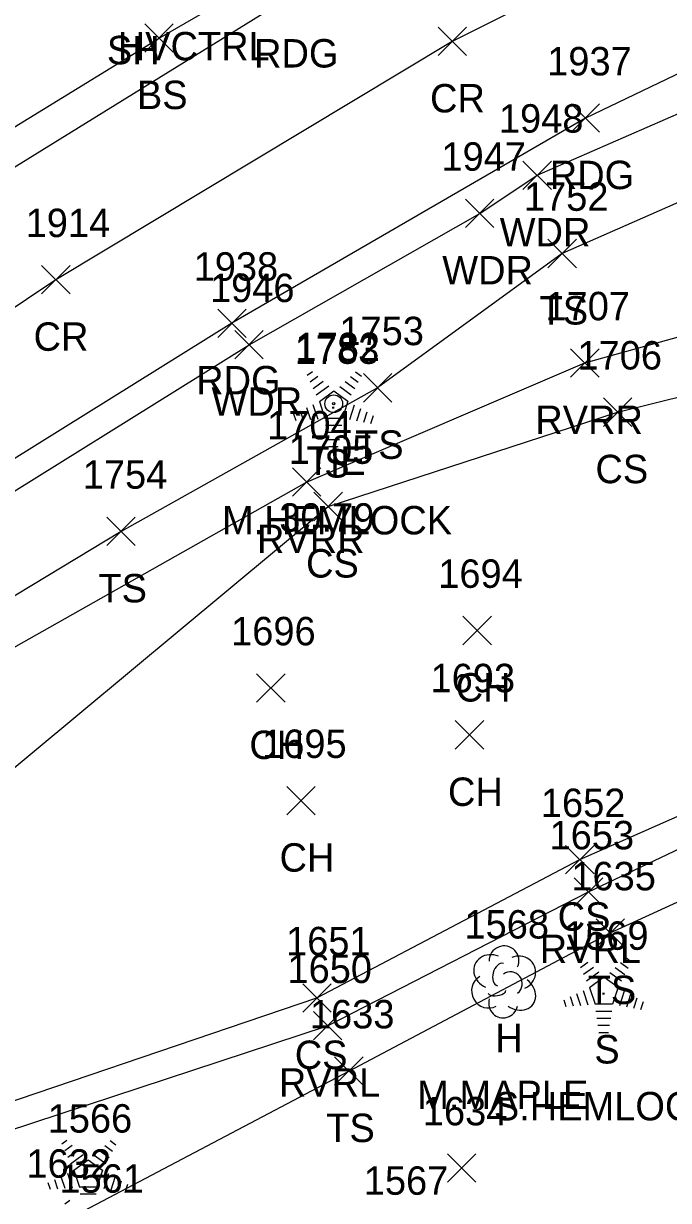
# Model space of a CAD drawing. Extents: x 1621633 to 1624015, y 417863 to 420979.
# Drawn here: x 1621720.8 to 1621766.2, y 417953.8 to 418036.6 of the extents above; entities that cross this region are included whole.
import ezdxf

# ---------------------------------------------------------------- set-up
doc = ezdxf.new("R2010")
doc.units = 0
for name, color, linetype in [('C_A', 7, 'Continuous'), ('C_C', 7, 'Continuous'), ('C_I', 7, 'Continuous'), ('CBP', 7, 'Continuous'), ('L_A', 7, 'Continuous'), ('L_C', 7, 'Continuous'), ('L_I', 7, 'Continuous'), ('L_TIC', 7, 'Continuous'), ('LAWA', 7, 'Continuous'), ('LAWE', 7, 'Continuous'), ('LELB', 7, 'Continuous'), ('LTC', 7, 'Continuous'), ('LTD', 7, 'Continuous'), ('P_A', 7, 'Continuous'), ('P_I', 7, 'Continuous'), ('P_TIC', 7, 'Continuous'), ('PEU', 7, 'Continuous'), ('PRC', 7, 'Continuous')]:
    doc.layers.add(name, color=color, linetype=linetype)

msp = doc.modelspace()

# ---------------------------------------------------------------- linework, layer by layer
at = {"layer": 'CBP'}
for radius in [0.625, 0.0833]:
    msp.add_circle((1621742.603, 418009.803), radius, dxfattribs=at)
at = {"layer": 'L_TIC'}
for points in [[(1621729.307, 418034.534), (1621731.307, 418036.534)], [(1621731.307, 418034.534), (1621729.307, 418036.534)], [(1621755.92, 418024.879), (1621757.92, 418026.879)], [(1621757.92, 418024.879), (1621755.92, 418026.879)], [(1621751.876, 418022.199), (1621753.876, 418024.199)], [(1621753.876, 418022.199), (1621751.876, 418024.199)], [(1621757.68, 418019.378), (1621759.68, 418021.378)], [(1621759.68, 418019.378), (1621757.68, 418021.378)], [(1621735.638, 418012.959), (1621737.638, 418014.959)], [(1621737.638, 418012.959), (1621735.638, 418014.959)], [(1621759.276, 418011.676), (1621761.276, 418013.676)], [(1621761.276, 418011.676), (1621759.276, 418013.676)], [(1621744.692, 418009.927), (1621746.692, 418011.927)], [(1621746.692, 418009.927), (1621744.692, 418011.927)], [(1621761.579, 418008.214), (1621763.579, 418010.214)], [(1621763.579, 418008.214), (1621761.579, 418010.214)], [(1621739.687, 418003.296), (1621741.687, 418005.296)], [(1621741.687, 418003.296), (1621739.687, 418005.296)], [(1621741.211, 418001.577), (1621743.211, 418003.577)], [(1621743.211, 418001.577), (1621741.211, 418003.577)], [(1621726.629, 417999.827), (1621728.629, 418001.827)], [(1621728.629, 417999.827), (1621726.629, 418001.827)], [(1621751.698, 417992.853), (1621753.698, 417994.853)], [(1621753.698, 417992.853), (1621751.698, 417994.853)], [(1621737.173, 417988.809), (1621739.173, 417990.809)], [(1621739.173, 417988.809), (1621737.173, 417990.809)], [(1621751.155, 417985.509), (1621753.155, 417987.509)], [(1621753.155, 417985.509), (1621751.155, 417987.509)], [(1621739.299, 417980.884), (1621741.299, 417982.884)], [(1621741.299, 417980.884), (1621739.299, 417982.884)], [(1621758.92, 417976.729), (1621760.92, 417978.729)], [(1621760.92, 417976.729), (1621758.92, 417978.729)], [(1621759.532, 417974.456), (1621761.532, 417976.456)], [(1621761.532, 417974.456), (1621759.532, 417976.456)], [(1621761.067, 417971.573), (1621763.067, 417973.573)], [(1621763.067, 417971.573), (1621761.067, 417973.573)], [(1621740.418, 417967.002), (1621742.418, 417969.002)], [(1621742.418, 417967.002), (1621740.418, 417969.002)], [(1621741.172, 417965.049), (1621743.172, 417967.049)], [(1621743.172, 417965.049), (1621741.172, 417967.049)], [(1621742.664, 417961.858), (1621744.664, 417963.858)], [(1621744.664, 417961.858), (1621742.664, 417963.858)], [(1621750.612, 417955.037), (1621752.612, 417957.037)], [(1621752.612, 417955.037), (1621750.612, 417957.037)]]:
    msp.add_lwpolyline(points, dxfattribs=at)
at = {"layer": 'LAWA'}
msp.add_lwpolyline([(1621679.191, 417971.595), (1621702.483, 417990.446), (1621715.012, 418000.477), (1621736.638, 418013.959), (1621752.876, 418023.199), (1621756.92, 418025.879), (1621771.105, 418032.081), (1621799.594, 418044.877), (1621821.796, 418051.595), (1621846.965, 418058.282), (1621864.113, 418063.689), (1621891.562, 418069.816), (1621913.254, 418074.106), (1621937.152, 418070.696)], dxfattribs=at)
at = {"layer": 'LAWE'}
for points in [[(1621694.469, 417944.857), (1621713.846, 417956.733), (1621742.172, 417966.049), (1621760.532, 417975.456), (1621777.237, 417983.398), (1621792.696, 417991.301), (1621817.095, 418001.163), (1621844.467, 418008.037), (1621871.363, 418013.308), (1621897.422, 418019.495), (1621922.912, 418028.804), (1621945.859, 418038.978), (1621969.359, 418051.535), (1621990.012, 418069.674), (1621996.064, 418084.217), (1621996.533, 418092.287)], [(1621682.822, 417967.998), (1621698.064, 417979.126), (1621716.448, 417990.621), (1621740.687, 418004.296), (1621760.276, 418012.676), (1621779.786, 418018.1), (1621807.782, 418023.044), (1621832.841, 418028.899), (1621852.452, 418034.783), (1621876.37, 418040.125), (1621904.646, 418043.594), (1621931.259, 418052.925), (1621950.617, 418064.927), (1621964.804, 418074.349), (1621971.864, 418081.724)]]:
    msp.add_lwpolyline(points, dxfattribs=at)
at = {"layer": 'LELB'}
for points in [[(1621664.034, 417989.432), (1621687.487, 418007.656), (1621711.941, 418024.269), (1621730.307, 418035.534), (1621752.55, 418048.381), (1621767.69, 418055.001), (1621798.303, 418066.249), (1621826.915, 418075.928), (1621858.253, 418085.298), (1621888.981, 418092.531), (1621914.256, 418098.407), (1621930.996, 418100.467)], [(1621694.018, 417945.604), (1621713.058, 417958.392), (1621741.418, 417968.002), (1621759.92, 417977.729), (1621776.332, 417984.988), (1621792.046, 417992.579), (1621816.284, 418002.68), (1621844.088, 418009.589), (1621869.849, 418015.692), (1621896.837, 418021.913), (1621921.805, 418030.632), (1621944.897, 418041.057), (1621968.773, 418053.066), (1621989.111, 418070.538), (1621994.262, 418084.512), (1621994.522, 418092.07)], [(1621714.218, 417979.319), (1621742.211, 418002.577), (1621762.579, 418009.214), (1621780.28, 418013.608), (1621808.258, 418019.376), (1621833.473, 418026.83), (1621853.516, 418030.646), (1621878.098, 418035.973), (1621904.446, 418042.094), (1621933.372, 418049.997), (1621951.553, 418063.416), (1621967.003, 418072.955), (1621972.682, 418081.713), (1621977.304, 418089.793)], [(1621870.082, 418049.389), (1621847.864, 418048.319), (1621821.87, 418043.443), (1621810.848, 418041.046), (1621801.708, 418037.161), (1621779.745, 418029.631), (1621758.68, 418020.378), (1621745.692, 418010.927), (1621727.629, 418000.827), (1621708.748, 417989.428), (1621682.341, 417970.694)], [(1621696.619, 417939.068), (1621723.715, 417952.351), (1621743.664, 417962.858), (1621762.067, 417972.573), (1621786.253, 417983.66), (1621806.904, 417990.669), (1621831.079, 418002.462), (1621857.774, 418009.445), (1621874.764, 418010.395)]]:
    msp.add_lwpolyline(points, dxfattribs=at)
at = {"layer": 'LTC'}
for p, q in [((1621740.742, 418011.82), (1621741.097, 418012.078)), ((1621744.14, 418012.061), (1621744.56, 418011.756)), ((1621740.952, 418011.355), (1621741.481, 418011.739)), ((1621741.161, 418010.889), (1621741.865, 418011.4)), ((1621743.398, 418011.364), (1621744.078, 418010.87)), ((1621743.769, 418011.713), (1621744.319, 418011.313)), ((1621741.371, 418010.423), (1621742.249, 418011.061)), ((1621741.595, 418009.968), (1621742.607, 418010.703)), ((1621742.607, 418010.703), (1621743.604, 418009.978)), ((1621743.027, 418011.016), (1621743.837, 418010.427)), ((1621740.685, 418009.533), (1621740.957, 418008.698)), ((1621741.141, 418009.749), (1621741.472, 418008.73)), ((1621741.595, 418009.968), (1621741.983, 418008.775)), ((1621743.604, 418009.978), (1621743.213, 418008.775)), ((1621744.042, 418009.707), (1621743.704, 418008.668)), ((1621739.775, 418009.1), (1621739.927, 418008.632)), ((1621740.23, 418009.316), (1621740.442, 418008.665)), ((1621743.213, 418008.775), (1621741.983, 418008.775)), ((1621744.486, 418009.457), (1621744.199, 418008.572)), ((1621744.931, 418009.207), (1621744.694, 418008.477)), ((1621745.375, 418008.956), (1621745.188, 418008.382)), ((1621743.175, 418008.275), (1621742.03, 418008.275)), ((1621743.091, 418007.775), (1621742.103, 418007.775)), ((1621743.007, 418007.275), (1621742.175, 418007.275)), ((1621742.923, 418006.775), (1621742.248, 418006.775)), ((1621759.753, 417970.597), (1621760.107, 417970.854)), ((1621763.151, 417970.837), (1621763.57, 417970.532)), ((1621759.962, 417970.131), (1621760.491, 417970.515)), ((1621760.172, 417969.665), (1621760.876, 417970.177)), ((1621760.381, 417969.2), (1621761.26, 417969.837)), ((1621762.038, 417969.792), (1621762.847, 417969.203)), ((1621762.409, 417970.14), (1621763.088, 417969.647)), ((1621762.78, 417970.489), (1621763.329, 417970.09)), ((1621760.606, 417968.745), (1621761.618, 417969.479)), ((1621761.618, 417969.479), (1621762.615, 417968.754)), ((1621759.696, 417968.309), (1621759.967, 417967.474)), ((1621760.151, 417968.525), (1621760.482, 417967.506)), ((1621760.606, 417968.745), (1621760.993, 417967.551)), ((1621762.615, 417968.754), (1621762.223, 417967.551)), ((1621763.052, 417968.483), (1621762.714, 417967.444)), ((1621763.497, 417968.233), (1621763.209, 417967.348)), ((1621758.785, 417967.876), (1621758.937, 417967.408)), ((1621759.241, 417968.092), (1621759.452, 417967.441)), ((1621762.223, 417967.551), (1621760.993, 417967.551)), ((1621763.941, 417967.983), (1621763.704, 417967.253)), ((1621764.386, 417967.732), (1621764.199, 417967.158)), ((1621762.185, 417967.051), (1621761.041, 417967.051)), ((1621762.101, 417966.551), (1621761.113, 417966.551)), ((1621762.018, 417966.051), (1621761.186, 417966.051)), ((1621761.934, 417965.551), (1621761.259, 417965.551)), ((1621723.455, 417957.734), (1621723.81, 417957.992)), ((1621723.665, 417957.269), (1621724.194, 417957.653)), ((1621726.482, 417957.626), (1621727.032, 417957.227)), ((1621726.854, 417957.975), (1621727.273, 417957.67)), ((1621723.874, 417956.803), (1621724.578, 417957.314)), ((1621724.084, 417956.337), (1621724.962, 417956.975)), ((1621724.309, 417955.882), (1621725.32, 417956.617)), ((1621725.32, 417956.617), (1621726.317, 417955.892)), ((1621725.74, 417956.93), (1621726.55, 417956.341)), ((1621726.111, 417957.278), (1621726.791, 417956.784)), ((1621724.309, 417955.882), (1621724.696, 417954.689)), ((1621726.317, 417955.892), (1621725.926, 417954.689)), ((1621722.488, 417955.013), (1621722.64, 417954.545)), ((1621722.943, 417955.23), (1621723.155, 417954.578)), ((1621723.399, 417955.447), (1621723.67, 417954.611)), ((1621723.854, 417955.663), (1621724.185, 417954.644)), ((1621726.755, 417955.621), (1621726.417, 417954.581)), ((1621727.199, 417955.37), (1621726.912, 417954.486)), ((1621727.644, 417955.12), (1621727.407, 417954.391)), ((1621728.088, 417954.87), (1621727.901, 417954.296)), ((1621725.926, 417954.689), (1621724.696, 417954.689)), ((1621725.888, 417954.189), (1621724.743, 417954.189)), ((1621723.663, 417953.505), (1621724.018, 417953.763))]:
    msp.add_line(p, q, dxfattribs=at)
at = {"layer": 'LTD'}
msp.add_line((1621754.542, 417969.18), (1621754.542, 417969.18), dxfattribs=at)
msp.add_line((1621754.542, 417969.18), (1621754.542, 417969.18), dxfattribs=at)
msp.add_arc((1621754.589, 417970.614), 1.047, 335.52715, 180.95627, dxfattribs=at)
for centre, major_axis, ratio, start_param, end_param in [((1621753.75, 417969.846), (1.21, -0.512), 0.895232, 1.570796, 4.712389), ((1621755.584, 417969.763), (-1.141, -0.483), 0.949671, 1.570796, 4.712389), ((1621754.334, 417969.638), (-0.208, -0.792), 0.645439, 3.141593, 6.283185), ((1621755.042, 417969.013), (-0.5, 0.667), 0.989748, 3.141593, 6.283185), ((1621753.459, 417968.471), (0.584, -1.042), 0.959034, 3.141593, 6.283185), ((1621755.542, 417968.347), (-1.09, 0.792), 0.841452, 1.570796, 4.712389), ((1621754.084, 417968.43), (-0.625, -0.083), 0.423636, 0, 3.141593), ((1621754.542, 417967.68), (0.265, 1.061), 0.942809, 1.570796, 4.712389)]:
    msp.add_ellipse(centre, major_axis=major_axis, ratio=ratio, start_param=start_param, end_param=end_param, dxfattribs=at)
at = {"layer": 'P_TIC'}
for points in [[(1621749.947, 418034.3), (1621751.947, 418036.3)], [(1621751.947, 418034.3), (1621749.947, 418036.3)], [(1621759.318, 418028.904), (1621761.318, 418030.904)], [(1621761.318, 418028.904), (1621759.318, 418030.904)], [(1621722.041, 418017.53), (1621724.041, 418019.53)], [(1621724.041, 418017.53), (1621722.041, 418019.53)], [(1621734.432, 418014.464), (1621736.432, 418016.464)], [(1621736.432, 418014.464), (1621734.432, 418016.464)]]:
    msp.add_lwpolyline(points, dxfattribs=at)
at = {"layer": 'PEU'}
for points in [[(1621666.087, 417987.333), (1621690.601, 418006.329), (1621714.112, 418022.734), (1621739.503, 418038.461), (1621766, 418052.456), (1621797.985, 418064.445), (1621829.098, 418075.197), (1621862.236, 418084.699), (1621894.034, 418092.423)], [(1621912.204, 418078.592), (1621880.997, 418070.288), (1621848.822, 418062.508), (1621818.735, 418053.659), (1621789.443, 418043.868), (1621760.318, 418029.904), (1621735.432, 418015.464), (1621709.615, 417999.398), (1621686.1, 417982.194), (1621676.517, 417973.897)]]:
    msp.add_lwpolyline(points, dxfattribs=at)
at = {"layer": 'PRC'}
msp.add_lwpolyline([(1621971.067, 418099.341), (1621938.438, 418093.726), (1621906.629, 418086.952), (1621874.869, 418079.941), (1621842.519, 418071.194), (1621811.531, 418061.42), (1621780.514, 418050.109), (1621750.947, 418035.3), (1621723.041, 418018.53), (1621696.18, 418000.53), (1621670.933, 417981.571)], dxfattribs=at)

# ---------------------------------------------------------------- texts
at = {"layer": 'C_A'}
for s, p in [('HVCTRL', (1621727.398, 418033.961)), ('TIE', (1621740.682, 418004.803))]:
    msp.add_text(s, height=2, dxfattribs=at).set_placement(p)
at = {"layer": 'C_C'}
msp.add_text('30.79', height=2, dxfattribs=at).set_placement((1621738.768, 418000.803))
at = {"layer": 'C_I'}
msp.add_text('1782', height=2, dxfattribs=at).set_placement((1621739.91, 418012.803))
at = {"layer": 'L_A'}
for s, p in [('SH', (1621726.634, 418033.689)), ('BS', (1621728.747, 418030.534)), ('WDR', (1621754.282, 418020.879)), ('WDR', (1621750.238, 418018.199)), ('TS', (1621757.089, 418015.378)), ('WDR', (1621734.001, 418008.959)), ('RVRR', (1621756.788, 418007.676)), ('TS', (1621744.102, 418005.927)), ('S', (1621741.933, 418004.612)), ('CS', (1621761.02, 418004.214)), ('RVRR', (1621737.198, 417999.296)), ('CS', (1621740.652, 417997.577)), ('TS', (1621726.038, 417995.827)), ('CH', (1621751.186, 417988.853)), ('CH', (1621736.661, 417984.809)), ('CH', (1621750.643, 417981.509)), ('CH', (1621738.787, 417976.884)), ('CS', (1621758.361, 417972.729)), ('RVRL', (1621757.099, 417970.456)), ('TS', (1621760.476, 417967.573)), ('H', (1621753.975, 417964.18)), ('CS', (1621739.859, 417963.002)), ('S', (1621760.943, 417963.388)), ('RVRL', (1621738.739, 417961.049)), ('TS', (1621742.073, 417957.858))]:
    msp.add_text(s, height=2, dxfattribs=at).set_placement(p)
at = {"layer": 'L_C'}
for s, p in [('M.HEMLOCK', (1621734.736, 418000.612)), ('M.MAPLE', (1621748.479, 417960.18)), ('S.HEMLOCK', (1621753.872, 417959.388))]:
    msp.add_text(s, height=2, dxfattribs=at).set_placement(p)
at = {"layer": 'L_I'}
for s, p in [('1948', (1621754.227, 418028.879)), ('1947', (1621750.183, 418026.199)), ('1752', (1621755.987, 418023.378)), ('1946', (1621733.89, 418016.959)), ('1707', (1621757.504, 418015.676)), ('1753', (1621742.999, 418013.927)), ('1783', (1621739.854, 418012.612)), ('1706', (1621759.753, 418012.214)), ('1704', (1621737.915, 418007.296)), ('1705', (1621739.44, 418005.577)), ('1754', (1621724.936, 418003.827)), ('1694', (1621749.957, 417996.853)), ('1696', (1621735.378, 417992.809)), ('1693', (1621749.415, 417989.509)), ('1695', (1621737.559, 417984.884)), ('1652', (1621757.18, 417980.729)), ('1653', (1621757.792, 417978.456)), ('1635', (1621759.327, 417975.573)), ('1568', (1621751.802, 417972.18)), ('1569', (1621758.809, 417971.388)), ('1651', (1621739.245, 417971.002)), ('1650', (1621739.345, 417969.049)), ('1633', (1621740.924, 417965.858)), ('1634', (1621748.872, 417959.037)), ('1566', (1621722.465, 417958.526)), ('1632', (1621720.975, 417955.351)), ('1561', (1621723.295, 417954.297)), ('1567', (1621744.715, 417954.152))]:
    msp.add_text(s, height=2, dxfattribs=at).set_placement(p)
at = {"layer": 'LTC'}
for p in [(1621742.49, 418009.716), (1621761.5, 417968.492), (1621725.203, 417955.63)]:
    msp.add_text('.', height=1.037, rotation=270, dxfattribs=at).set_placement(p)
at = {"layer": 'P_A'}
for s, p in [('RDG', (1621736.991, 418033.461)), ('CR', (1621749.38, 418030.3)), ('RDG', (1621757.806, 418024.904)), ('CR', (1621721.474, 418013.53)), ('RDG', (1621732.92, 418010.464))]:
    msp.add_text(s, height=2, dxfattribs=at).set_placement(p)
at = {"layer": 'P_I'}
for s, p in [('1937', (1621757.625, 418032.904)), ('1914', (1621720.915, 418021.53)), ('1938', (1621732.739, 418018.464))]:
    msp.add_text(s, height=2, dxfattribs=at).set_placement(p)

doc.saveas('drawing.dxf')
